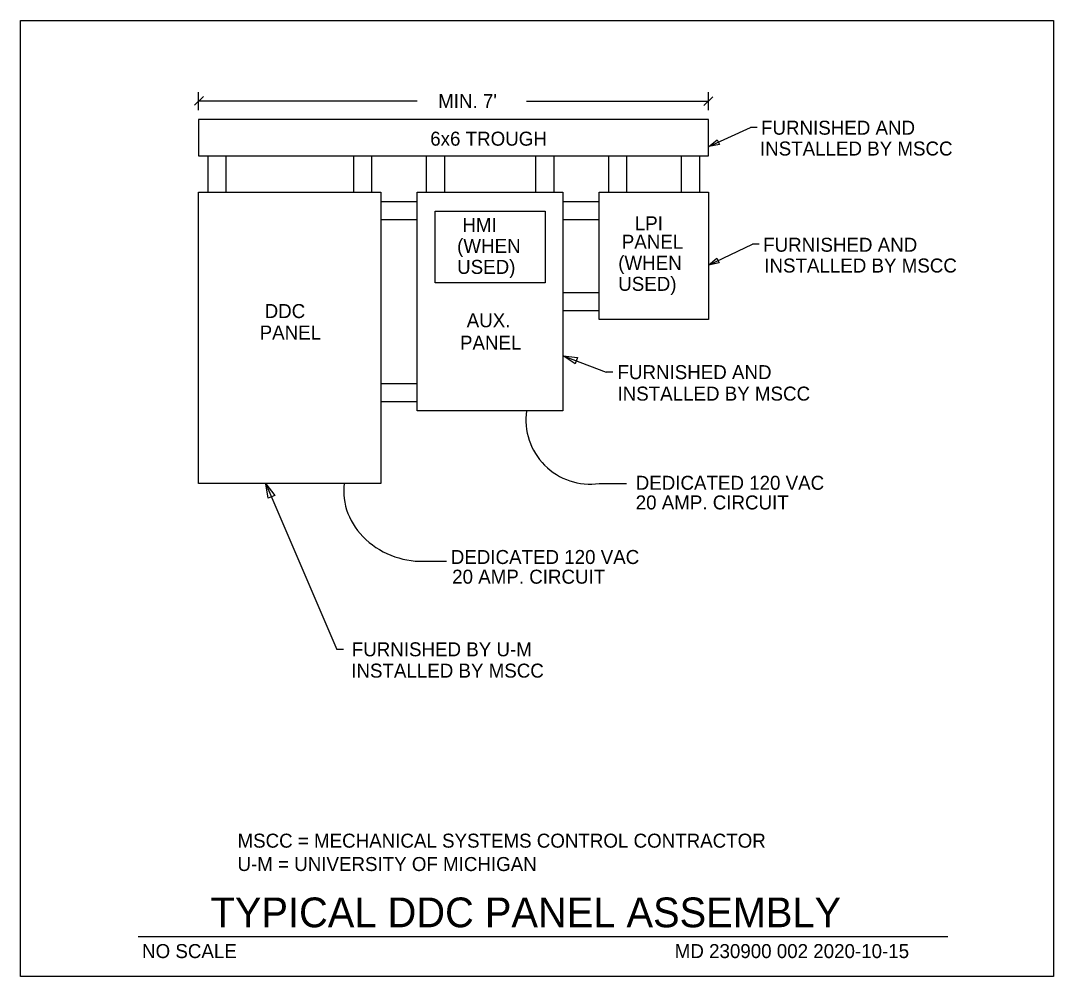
# Model space of a CAD drawing. Extents: x 10178.8 to 10227.9, y 10065.6 to 10111.1.
import ezdxf

# ---------------------------------------------------------------- set-up
doc = ezdxf.new("R2010")
doc.units = 0
for name, color, linetype in [('Default', 7, 'Continuous'), ('G-ANNO-CELL', 7, 'Continuous'), ('G-DETL-GRID', 7, 'Continuous'), ('G-DETL-LINE', 7, 'Continuous'), ('G-DETL-TEXT', 7, 'Continuous')]:
    doc.layers.add(name, color=color, linetype=linetype)

# ---------------------------------------------------------------- blocks, each defined once
blk = doc.blocks.new('ARROW')
at = {"layer": 'Default'}
blk.add_line((-0.000496, 0), (0, 0), dxfattribs=at)

msp = doc.modelspace()

# ---------------------------------------------------------------- linework, layer by layer
at = {"layer": 'G-ANNO-CELL'}
msp.add_line((10184.395, 10067.55), (10222.92, 10067.55), dxfattribs=at)
at = {"layer": 'G-DETL-GRID'}
msp.add_lwpolyline([(10178.798, 10111.146), (10227.941, 10111.146), (10227.941, 10065.646), (10178.798, 10065.646)], close=True, dxfattribs=at)
at = {"layer": 'G-DETL-LINE'}
for p, q in [((10187.267, 10106.443), (10187.267, 10104.71)), ((10211.533, 10106.443), (10187.267, 10106.443)), ((10211.533, 10104.71), (10211.533, 10106.443)), ((10187.267, 10104.71), (10211.533, 10104.71)), ((10187.7, 10104.71), (10187.7, 10102.977)), ((10188.567, 10104.71), (10188.567, 10102.977)), ((10194.633, 10104.71), (10194.633, 10102.977)), ((10195.5, 10104.71), (10195.5, 10102.977)), ((10198.1, 10104.71), (10198.1, 10102.977)), ((10198.967, 10104.71), (10198.967, 10102.977)), ((10203.3, 10104.71), (10203.3, 10102.977)), ((10204.167, 10104.71), (10204.167, 10102.977)), ((10206.767, 10104.71), (10206.767, 10102.977)), ((10207.633, 10104.71), (10207.633, 10102.977)), ((10210.233, 10104.71), (10210.233, 10102.977)), ((10211.1, 10104.71), (10211.1, 10102.977)), ((10187.267, 10102.977), (10195.933, 10102.977)), ((10187.267, 10089.11), (10187.267, 10102.977)), ((10195.933, 10102.977), (10195.933, 10089.11)), ((10197.667, 10102.977), (10204.6, 10102.977)), ((10197.667, 10092.577), (10197.667, 10102.977)), ((10204.6, 10102.977), (10204.6, 10092.577)), ((10206.333, 10096.91), (10206.333, 10102.977)), ((10206.333, 10102.977), (10211.533, 10102.977)), ((10211.533, 10102.977), (10211.533, 10096.91)), ((10195.933, 10102.543), (10197.667, 10102.543)), ((10204.6, 10102.543), (10206.333, 10102.543)), ((10195.933, 10101.677), (10197.667, 10101.677)), ((10204.6, 10101.677), (10206.333, 10101.677)), ((10204.6, 10098.21), (10206.333, 10098.21)), ((10204.6, 10097.343), (10206.333, 10097.343)), ((10211.533, 10096.91), (10206.333, 10096.91)), ((10195.933, 10093.877), (10197.667, 10093.877)), ((10195.933, 10093.01), (10197.667, 10093.01)), ((10204.6, 10092.577), (10197.667, 10092.577)), ((10195.933, 10089.11), (10187.267, 10089.11)), ((10198.186, 10085.417), (10199.058, 10085.417))]:
    msp.add_line(p, q, dxfattribs=at)
msp.add_lwpolyline([(10198.529, 10102.081), (10203.751, 10102.081), (10203.751, 10098.657), (10198.529, 10098.657)], close=True, dxfattribs=at)
msp.add_arc((10205.9, 10092.143), 3.064, 171.8699, 278.1301, dxfattribs=at)
msp.add_ellipse((10197.639, 10088.5), major_axis=(-3.358, 0.984), ratio=0.873556, start_param=0.125143, end_param=1.979734, dxfattribs=at)
at = {"layer": 'G-DETL-TEXT'}
for p, q in [((10187.267, 10106.877), (10187.267, 10107.743)), ((10211.533, 10106.877), (10211.533, 10107.743)), ((10187.074, 10107.118), (10187.493, 10107.536)), ((10197.667, 10107.31), (10187.267, 10107.31)), ((10202.867, 10107.31), (10211.533, 10107.31)), ((10211.316, 10107.104), (10211.734, 10107.522)), ((10211.542, 10105.147), (10213.524, 10106.063)), ((10213.841, 10106.063), (10213.524, 10106.063)), ((10211.528, 10099.507), (10213.627, 10100.498)), ((10213.944, 10100.498), (10213.627, 10100.498)), ((10204.619, 10095.192), (10206.665, 10094.413)), ((10206.982, 10094.413), (10206.665, 10094.413)), ((10190.473, 10089.091), (10193.839, 10081.212)), ((10194.156, 10081.212), (10193.839, 10081.212))]:
    msp.add_line(p, q, dxfattribs=at)
for points in [[(10212.048, 10105.243), (10211.542, 10105.147), (10211.943, 10105.47)], [(10212.033, 10099.608), (10211.528, 10099.507), (10211.927, 10099.834)], [(10205.183, 10094.799), (10204.619, 10095.192), (10205.301, 10095.11)], [(10190.582, 10088.413), (10190.473, 10089.091), (10190.888, 10088.544)]]:
    msp.add_lwpolyline(points, close=True, dxfattribs=at)

# ---------------------------------------------------------------- block references
at = {"layer": 'G-DETL-LINE', "xscale": 2620.4724409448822, "yscale": 2620.4724409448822}
msp.add_blockref('ARROW', (10207.633, 10089.11), dxfattribs=at)

# ---------------------------------------------------------------- texts
at = {"layer": 'G-ANNO-CELL'}
for s, height, p in [('TYPICAL DDC PANEL ASSEMBLY', 1.41667, (10187.836, 10067.983)), ('NO SCALE', 0.6667, (10184.576, 10066.515))]:
    msp.add_text(s, height=height, dxfattribs=at).set_placement(p)
at = {"layer": 'G-DETL-LINE'}
msp.add_text('INSTALLED BY MSCC', height=0.66667, dxfattribs=at).set_placement((10214.185, 10099.153))
at = {"layer": 'G-DETL-TEXT'}
for s, height, p in [("MIN. 7'", 0.6667, (10198.666, 10106.985)), ('FURNISHED AND', 0.66667, (10214.03, 10105.715)), ('6x6 TROUGH', 0.6667, (10198.289, 10105.193)), ('INSTALLED BY MSCC', 0.66667, (10213.979, 10104.724)), (' HMI', 0.6667, (10199.569, 10101.089)), ('LPI', 0.6667, (10208.023, 10101.162)), ('(WHEN', 0.6667, (10199.569, 10100.089)), ('PANEL', 0.6667, (10207.404, 10100.285)), ('FURNISHED AND', 0.66667, (10214.133, 10100.143)), ('USED)', 0.6667, (10199.569, 10099.089)), ('(WHEN', 0.6667, (10207.235, 10099.282)), ('USED)', 0.6667, (10207.235, 10098.282)), ('DDC', 0.6667, (10190.409, 10096.986)), ('AUX.', 0.6667, (10200.024, 10096.547)), ('PANEL', 0.6667, (10190.171, 10095.965)), ('PANEL', 0.6667, (10199.704, 10095.479)), ('FURNISHED AND', 0.66667, (10207.2, 10094.077)), ('INSTALLED BY MSCC', 0.66667, (10207.2, 10093.056)), ('DEDICATED 120 VAC', 0.66667, (10208.067, 10088.81)), ('20 AMP. CIRCUIT', 0.66667, (10208.067, 10087.874)), ('DEDICATED 120 VAC', 0.66667, (10199.267, 10085.277)), ('20 AMP. CIRCUIT', 0.66667, (10199.333, 10084.34)), ('FURNISHED BY U-M', 0.66667, (10194.556, 10080.882)), ('INSTALLED BY MSCC', 0.66667, (10194.53, 10079.867)), ('MSCC = MECHANICAL SYSTEMS CONTROL CONTRACTOR', 0.66667, (10189.117, 10071.772)), ('U-M = UNIVERSITY OF MICHIGAN', 0.66667, (10189.117, 10070.66)), ('MD 230900 002 2020-10-15', 0.66667, (10209.924, 10066.515))]:
    msp.add_text(s, height=height, dxfattribs=at).set_placement(p)

doc.saveas('drawing.dxf')
